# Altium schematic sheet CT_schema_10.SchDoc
size 281 x 153 mm
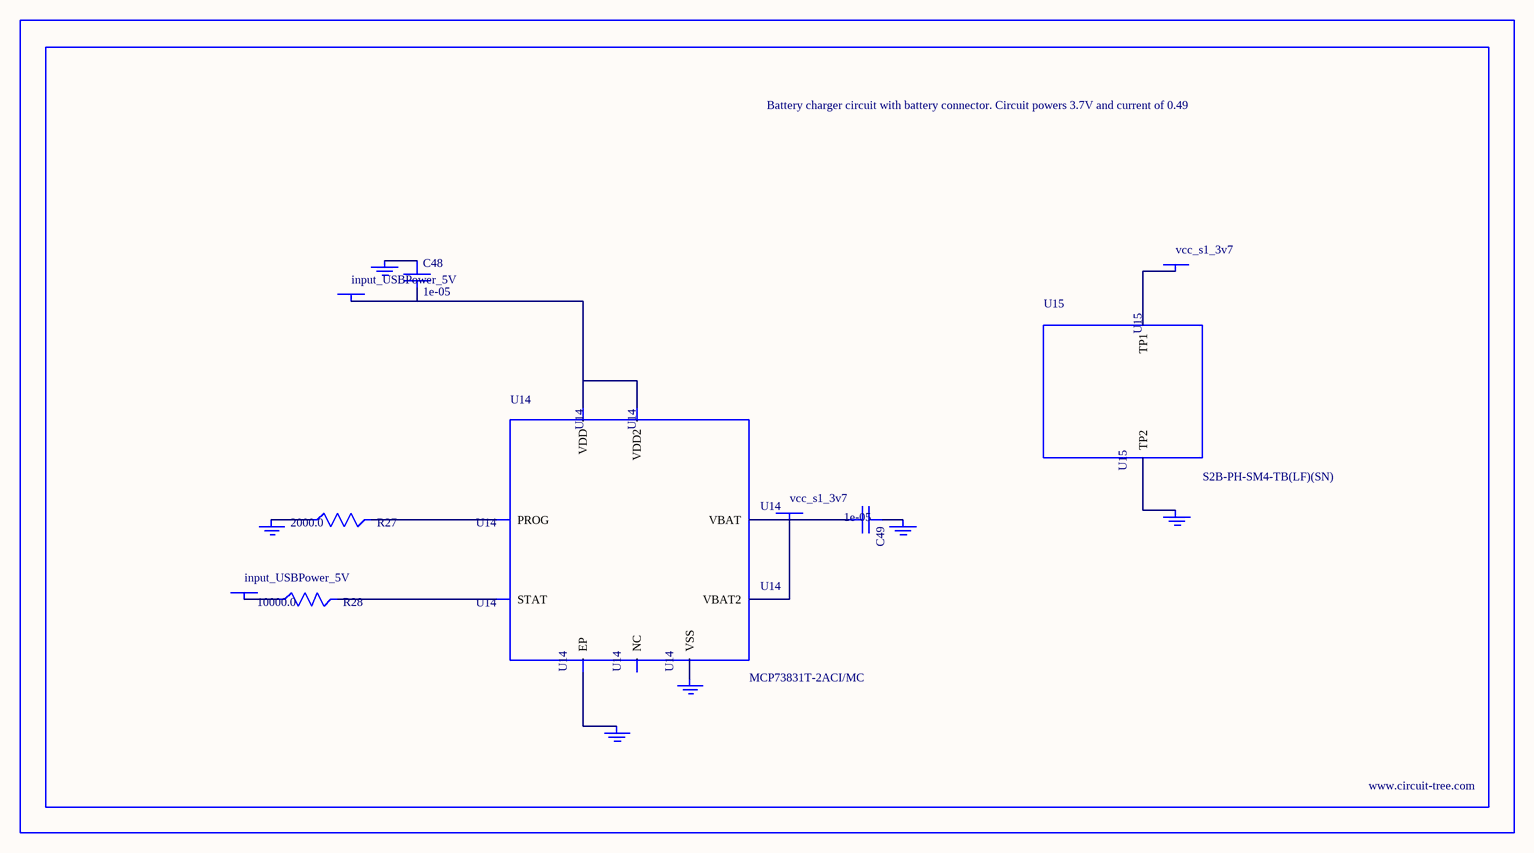
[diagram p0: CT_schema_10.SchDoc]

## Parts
BORDER9  (no value)
C48  1e-05  [C1206]
C49  1e-05  [C1206]
GND_INSTANCE_9_0  (no value)
GND_INSTANCE_9_1  (no value)
GND_INSTANCE_9_2  (no value)
GND_INSTANCE_9_3  (no value)
GND_INSTANCE_9_4  (no value)
GND_INSTANCE_9_5  (no value)
POWER_INSTANCE_9_0  input_USBPower_5V
POWER_INSTANCE_9_1  input_USBPower_5V
POWER_INSTANCE_9_2  vcc_s1_3v7
POWER_INSTANCE_9_3  vcc_s1_3v7
R27  2000.0  [R0603]
R28  10000.0  [R0603]
U14  MCP73831T-2ACI/MC  [DFN8_2X3MC]
U15  S2B-PH-SM4-TB(LF)(SN)  [JST-2-SMD]

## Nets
NetC48_1: C48.1 GND_INSTANCE_9_0.0(GND)
NetC48_2: C48.2 POWER_INSTANCE_9_0.0(PWR) U14.1(VDD) U14.2(VDD2)
NetC49_1: C49.1 GND_INSTANCE_9_1.0(GND)
NetC49_2: C49.2 POWER_INSTANCE_9_2.0(PWR) U14.3(VBAT) U14.4(VBAT2)
NetGND_INSTANCE_9_2_0: GND_INSTANCE_9_2.0(GND) R27.1
NetGND_INSTANCE_9_3_0: GND_INSTANCE_9_3.0(GND) U14.9(EP)
NetGND_INSTANCE_9_4_0: GND_INSTANCE_9_4.0(GND) U14.6(VSS)
NetGND_INSTANCE_9_5_0: GND_INSTANCE_9_5.0(GND) U15.2(TP2)
NetPOWER_INSTANCE_9_1_0: POWER_INSTANCE_9_1.0(PWR) R28.1
NetPOWER_INSTANCE_9_3_0: POWER_INSTANCE_9_3.0(PWR) U15.1(TP1)
NetR27_2: R27.2 U14.8(PROG)
NetR28_2: R28.2 U14.5(STAT)

Not connected (* = marked no-connect by the designer): U14 7(NC)

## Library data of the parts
BORDER9 = BORDER_PAGE9
C48 C49 = C1206C106K3RACTU
GND_INSTANCE_9_0-GND_INSTANCE_9_5 = GND
POWER_INSTANCE_9_0-POWER_INSTANCE_9_3 = PWR
R27 = RC0603JR-072KL
R28 = RC0603JR-0710KL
